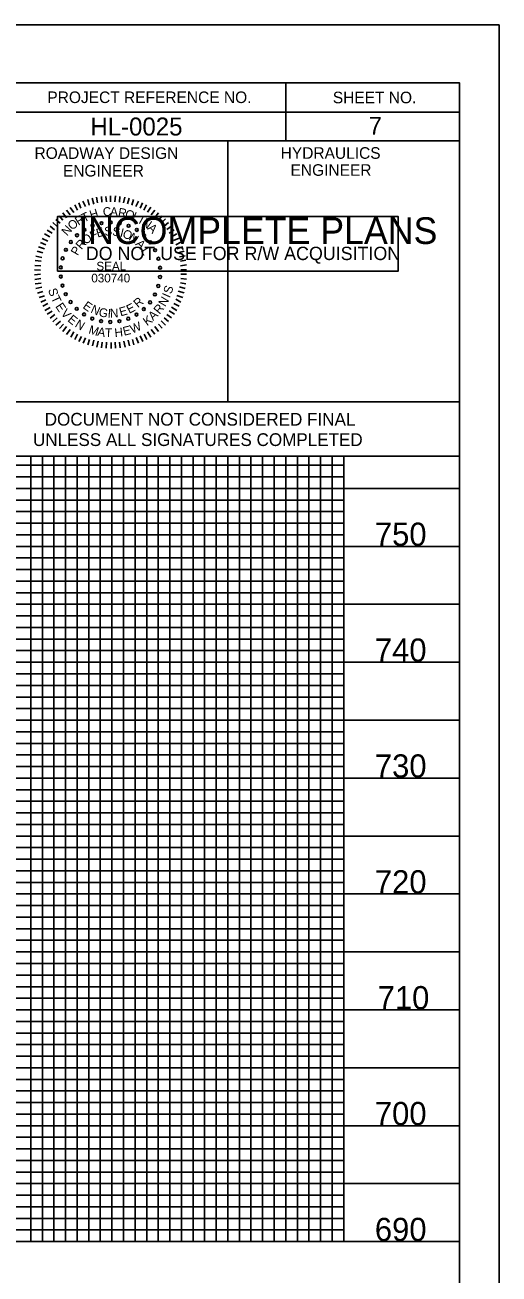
# Model space of a CAD drawing. Extents: x 1524869 to 1526553, y 501099 to 502199.
# Drawn here: x 1526349 to 1526553, y 501660 to 502199 of the extents above; entities that cross this region are included whole.
import ezdxf

# ---------------------------------------------------------------- set-up
doc = ezdxf.new("R2010")
doc.units = 0
for name, color, linetype in [('Exist Vertical Profile Vertical Axis Label', 7, 'Continuous'), ('Old_Level_9', 7, 'Continuous'), ('Sheet Data Field CELL', 7, 'Continuous'), ('Sheet Plot Border Outside CELL', 7, 'Continuous'), ('Sheet Profile CELL', 7, 'Continuous'), ('Sheet Profile Grid Major CELL', 7, 'Continuous'), ('Sheet Profile Grid Middle CELL', 7, 'Continuous'), ('Sheet Profile Grid Minor CELL', 7, 'Continuous'), ('Sheet Sticker Exception Certification CELL', 7, 'Continuous'), ('Sheet Sticker Incomplete CELL', 7, 'Continuous')]:
    doc.layers.add(name, color=color, linetype=linetype)

msp = doc.modelspace()

# ---------------------------------------------------------------- linework, layer by layer
at = {"layer": 'Old_Level_9'}
for p, q in [((1526371.83, 502121.79), (1526372.73, 502119.49)), ((1526373.53, 502122.59), (1526374.73, 502120.19)), ((1526375.63, 502123.19), (1526376.33, 502120.79)), ((1526377.53, 502123.79), (1526378.23, 502121.29)), ((1526379.43, 502124.19), (1526379.93, 502121.79)), ((1526381.53, 502124.49), (1526381.73, 502122.09)), ((1526383.43, 502124.59), (1526383.73, 502122.19)), ((1526385.53, 502124.79), (1526385.53, 502122.19)), ((1526387.63, 502124.79), (1526387.33, 502122.19)), ((1526389.53, 502124.49), (1526389.33, 502122.09)), ((1526391.63, 502124.19), (1526391.13, 502121.79)), ((1526393.53, 502123.79), (1526392.83, 502121.39)), ((1526395.43, 502123.19), (1526394.73, 502120.79)), ((1526397.53, 502122.59), (1526396.33, 502120.19)), ((1526399.23, 502121.79), (1526398.33, 502119.49)), ((1526364.93, 502117.49), (1526366.53, 502115.39)), ((1526366.53, 502118.69), (1526368.03, 502116.69)), ((1526368.13, 502119.79), (1526369.63, 502117.59)), ((1526370.03, 502120.99), (1526371.23, 502118.59)), ((1526401.03, 502120.99), (1526399.83, 502118.59)), ((1526402.93, 502119.99), (1526401.43, 502117.79)), ((1526404.53, 502118.69), (1526403.03, 502116.69)), ((1526406.13, 502117.49), (1526404.53, 502115.49)), ((1526359.43, 502111.69), (1526361.33, 502110.09)), ((1526360.53, 502113.29), (1526362.43, 502111.59)), ((1526361.93, 502114.69), (1526363.73, 502112.99)), ((1526363.33, 502116.19), (1526364.93, 502114.29)), ((1526407.73, 502116.19), (1526406.13, 502114.39)), ((1526409.13, 502114.89), (1526407.33, 502112.99)), ((1526410.53, 502113.29), (1526408.63, 502111.69)), ((1526411.83, 502111.69), (1526409.73, 502110.29)), ((1526356.03, 502106.49), (1526358.43, 502105.29)), ((1526357.03, 502108.39), (1526359.23, 502107.09)), ((1526358.13, 502109.99), (1526360.33, 502108.69)), ((1526412.93, 502110.09), (1526410.83, 502108.69)), ((1526414.03, 502108.39), (1526411.83, 502107.09)), ((1526415.03, 502106.59), (1526412.63, 502105.49)), ((1526353.83, 502100.89), (1526356.33, 502100.19)), ((1526354.43, 502102.79), (1526357.03, 502101.99)), ((1526355.23, 502104.69), (1526357.63, 502103.69)), ((1526415.83, 502104.89), (1526413.63, 502103.69)), ((1526416.63, 502102.79), (1526414.03, 502101.99)), ((1526417.23, 502100.89), (1526414.73, 502100.19)), ((1526352.83, 502094.79), (1526355.43, 502094.69)), ((1526353.03, 502096.89), (1526355.53, 502096.59)), ((1526353.33, 502098.79), (1526355.83, 502098.29)), ((1526417.73, 502098.99), (1526415.23, 502098.49)), ((1526418.03, 502097.09), (1526415.63, 502096.59)), ((1526418.23, 502094.99), (1526415.63, 502094.69)), ((1526352.73, 502092.89), (1526355.23, 502092.69)), ((1526352.73, 502090.79), (1526355.23, 502090.99)), ((1526418.33, 502092.89), (1526415.83, 502092.89)), ((1526418.33, 502090.99), (1526415.83, 502090.99)), ((1526352.83, 502088.79), (1526355.43, 502089.09)), ((1526353.03, 502086.79), (1526355.53, 502087.19)), ((1526353.33, 502084.79), (1526355.83, 502085.39)), ((1526417.73, 502084.89), (1526415.23, 502085.59)), ((1526418.03, 502086.79), (1526415.63, 502087.29)), ((1526418.23, 502088.89), (1526415.83, 502089.09)), ((1526353.93, 502082.89), (1526356.33, 502083.49)), ((1526354.63, 502080.99), (1526357.03, 502081.69)), ((1526355.43, 502078.99), (1526357.63, 502079.99)), ((1526415.83, 502078.99), (1526413.63, 502080.19)), ((1526416.63, 502080.99), (1526414.03, 502081.89)), ((1526417.23, 502082.99), (1526414.73, 502083.69)), ((1526356.23, 502077.29), (1526358.43, 502078.39)), ((1526357.13, 502075.39), (1526359.43, 502076.59)), ((1526358.13, 502073.79), (1526360.33, 502075.09)), ((1526359.43, 502071.99), (1526361.43, 502073.59)), ((1526411.83, 502072.19), (1526409.73, 502073.59)), ((1526413.13, 502073.79), (1526410.83, 502075.19)), ((1526414.03, 502075.39), (1526411.83, 502076.79)), ((1526415.03, 502077.29), (1526412.83, 502078.39)), ((1526360.63, 502070.39), (1526362.53, 502072.19)), ((1526361.93, 502068.99), (1526363.83, 502070.69)), ((1526363.53, 502067.59), (1526365.13, 502069.49)), ((1526364.93, 502066.29), (1526366.53, 502068.39)), ((1526406.23, 502066.29), (1526404.53, 502068.39)), ((1526407.73, 502067.69), (1526406.13, 502069.49)), ((1526409.13, 502068.99), (1526407.33, 502070.89)), ((1526410.53, 502070.59), (1526408.63, 502072.19)), ((1526366.53, 502064.99), (1526368.03, 502067.09)), ((1526368.33, 502063.89), (1526369.63, 502066.09)), ((1526370.03, 502062.89), (1526371.23, 502065.19)), ((1526371.83, 502061.99), (1526372.93, 502064.19)), ((1526373.73, 502061.19), (1526374.73, 502063.59)), ((1526375.63, 502060.49), (1526376.43, 502062.89)), ((1526377.73, 502060.09), (1526378.23, 502062.49)), ((1526393.63, 502060.09), (1526393.03, 502062.49)), ((1526395.53, 502060.49), (1526394.93, 502062.89)), ((1526397.53, 502061.19), (1526396.53, 502063.69)), ((1526399.43, 502061.99), (1526398.33, 502064.39)), ((1526401.13, 502062.89), (1526400.03, 502065.19)), ((1526402.93, 502063.89), (1526401.43, 502066.09)), ((1526404.53, 502065.19), (1526403.03, 502067.19)), ((1526379.63, 502059.59), (1526380.13, 502062.09)), ((1526381.53, 502059.29), (1526381.83, 502061.69)), ((1526383.63, 502059.09), (1526383.73, 502061.69)), ((1526385.73, 502058.99), (1526385.73, 502061.49)), ((1526387.63, 502059.09), (1526387.43, 502061.69)), ((1526389.63, 502059.29), (1526389.33, 502061.69)), ((1526391.73, 502059.59), (1526391.23, 502062.09))]:
    msp.add_line(p, q, dxfattribs=at)
for centre in [(1526377.76, 502111.96), (1526381.58, 502113.03), (1526385.53, 502113.38), (1526389.48, 502113), (1526393.29, 502111.9), (1526368.35, 502104.91), (1526371.03, 502107.83), (1526374.2, 502110.2), (1526396.83, 502110.12), (1526399.98, 502107.71), (1526366.25, 502101.54), (1526402.64, 502104.77), (1526404.72, 502101.39), (1526364.8, 502097.85), (1526406.13, 502097.69), (1526364.04, 502089.99), (1526364.05, 502093.96), (1526406.83, 502089.82), (1526406.85, 502093.79), (1526364.75, 502086.09), (1526406.09, 502085.93), (1526366.17, 502082.39), (1526368.25, 502079.01), (1526402.54, 502078.87), (1526404.64, 502082.24), (1526370.91, 502076.07), (1526374.06, 502073.66), (1526396.68, 502073.58), (1526399.86, 502075.95), (1526377.6, 502071.88), (1526381.41, 502070.78), (1526385.36, 502070.4), (1526389.31, 502070.75), (1526393.13, 502071.82)]:
    msp.add_circle(centre, 0.63, dxfattribs=at)
at = {"layer": 'Sheet Plot Border Outside CELL'}
msp.add_lwpolyline([(1524869.08, 501098.56), (1526553.08, 501098.56), (1526553.08, 502198.56), (1524869.08, 502198.56)], close=True, dxfattribs=at)
at = {"layer": 'Sheet Profile CELL'}
for p, q in [((1526461.08, 502173.51), (1526461.08, 502148.51)), ((1526336.03, 502161.01), (1526536.08, 502161.01)), ((1526436.08, 502148.51), (1526436.08, 502036.06)), ((1525036.08, 501673.56), (1526536.08, 501673.56))]:
    msp.add_line(p, q, dxfattribs=at)
for points in [[(1526536.08, 502173.56), (1525036.08, 502173.56), (1525036.08, 501123.56), (1526536.08, 501123.56)], [(1526336.03, 502173.56), (1526536.08, 502173.56), (1526536.08, 502148.51), (1526336.03, 502148.51)], [(1526336.03, 502148.51), (1526436.08, 502148.51), (1526436.08, 502036.01), (1526336.03, 502036.01)], [(1526436.08, 502148.51), (1526536.08, 502148.51), (1526536.08, 502036.01), (1526436.08, 502036.01)]]:
    msp.add_lwpolyline(points, close=True, dxfattribs=at)
at = {"layer": 'Sheet Profile Grid Major CELL'}
for points in [[(1525986.08, 501673.56), (1526036.08, 501673.56), (1526036.08, 502173.56), (1526086.08, 502173.56), (1526086.08, 501673.56), (1526136.08, 501673.56), (1526136.08, 502173.56), (1526186.08, 502173.56), (1526186.08, 501673.56), (1526236.08, 501673.56), (1526236.08, 502173.56), (1526286.08, 502173.56), (1526286.08, 501673.56), (1526336.08, 501673.56), (1526336.08, 502173.56), (1526362.38, 502173.56)], [(1526486.08, 502012.51), (1526486.08, 501673.56), (1526536.08, 501673.56), (1526536.08, 502023.56)], [(1526386.08, 502012.51), (1526386.08, 501673.56), (1526436.08, 501673.56), (1526436.08, 501673.56), (1526436.08, 502012.51)], [(1526536.08, 501973.56), (1525036.08, 501973.56), (1525036.08, 501923.56), (1526536.08, 501923.56)], [(1526536.08, 501873.56), (1525036.08, 501873.56), (1525036.08, 501823.56), (1526536.08, 501823.56)], [(1526536.08, 501773.56), (1525036.08, 501773.56), (1525036.08, 501773.56), (1525036.08, 501723.56), (1526536.08, 501723.56)]]:
    msp.add_lwpolyline(points, dxfattribs=at)
at = {"layer": 'Sheet Profile Grid Middle CELL'}
for points in [[(1526011.08, 501673.56), (1526061.08, 501673.56), (1526061.08, 502173.56), (1526111.08, 502173.56), (1526111.08, 501673.56), (1526161.08, 501673.56), (1526161.08, 502173.56), (1526211.08, 502173.56), (1526211.08, 501673.56), (1526261.08, 501673.56), (1526261.08, 502173.56), (1526311.08, 502173.56), (1526311.08, 501673.56), (1526361.08, 501673.56), (1526361.08, 502012.51)], [(1526361.08, 501936.36), (1526361.08, 501673.56), (1526411.08, 501673.56), (1526411.08, 502012.51)], [(1526411.08, 501936.36), (1526411.08, 501673.56), (1526461.08, 501673.56), (1526461.08, 502012.51)], [(1526536.08, 501998.56), (1525036.08, 501998.56), (1525036.08, 501948.56), (1526361.08, 501948.56)], [(1526361.08, 501948.56), (1526536.08, 501948.56)], [(1526536.08, 501898.56), (1525036.08, 501898.56), (1525036.08, 501848.56), (1526536.08, 501848.56)], [(1526536.08, 501798.56), (1525036.08, 501798.56), (1525036.08, 501748.56), (1526536.08, 501748.56)], [(1526536.08, 501698.56), (1525036.08, 501698.56)]]:
    msp.add_lwpolyline(points, dxfattribs=at)
at = {"layer": 'Sheet Profile Grid Minor CELL'}
for p, q in [((1526036.08, 502008.56), (1526486.08, 502008.56)), ((1526486.08, 501988.56), (1526036.08, 501988.56)), ((1526036.08, 501983.56), (1526486.08, 501983.56)), ((1526486.08, 501963.56), (1526036.08, 501963.56)), ((1526036.08, 501958.56), (1526486.08, 501958.56)), ((1526486.08, 501938.56), (1526036.08, 501938.56)), ((1526036.08, 501933.56), (1526486.08, 501933.56)), ((1526486.08, 501928.56), (1526036.08, 501928.56)), ((1526036.08, 501918.56), (1526486.08, 501918.56)), ((1526486.08, 501913.56), (1526036.08, 501913.56)), ((1526036.08, 501908.56), (1526486.08, 501908.56)), ((1526486.08, 501903.56), (1526036.08, 501903.56)), ((1526036.08, 501893.56), (1526486.08, 501893.56)), ((1526486.08, 501888.56), (1526036.08, 501888.56)), ((1526036.08, 501883.56), (1526486.08, 501883.56)), ((1526486.08, 501878.56), (1526036.08, 501878.56)), ((1526036.08, 501868.56), (1526486.08, 501868.56)), ((1526486.08, 501863.56), (1526036.08, 501863.56)), ((1526036.08, 501858.56), (1526486.08, 501858.56)), ((1526486.08, 501853.56), (1526036.08, 501853.56)), ((1526036.08, 501843.56), (1526486.08, 501843.56)), ((1526486.08, 501838.56), (1526036.08, 501838.56)), ((1526036.08, 501833.56), (1526486.08, 501833.56)), ((1526486.08, 501828.56), (1526036.08, 501828.56)), ((1526036.08, 501818.56), (1526486.08, 501818.56)), ((1526486.08, 501813.56), (1526036.08, 501813.56)), ((1526036.08, 501808.56), (1526486.08, 501808.56)), ((1526486.08, 501803.56), (1526036.08, 501803.56)), ((1526036.08, 501793.56), (1526486.08, 501793.56)), ((1526486.08, 501788.56), (1526036.08, 501788.56)), ((1526486.08, 501783.56), (1526036.08, 501783.56)), ((1526486.08, 501778.56), (1526036.08, 501778.56)), ((1526036.08, 501768.56), (1526486.08, 501768.56)), ((1526486.08, 501763.56), (1526036.08, 501763.56)), ((1526036.08, 501758.56), (1526486.08, 501758.56)), ((1526486.08, 501753.56), (1526036.08, 501753.56)), ((1526036.08, 501743.56), (1526486.08, 501743.56)), ((1526486.08, 501738.56), (1526036.08, 501738.56)), ((1526036.08, 501733.56), (1526486.08, 501733.56)), ((1526486.08, 501728.56), (1526036.08, 501728.56)), ((1526036.08, 501718.56), (1526486.08, 501718.56)), ((1526486.08, 501713.56), (1526036.08, 501713.56)), ((1526036.08, 501708.56), (1526486.08, 501708.56)), ((1526486.08, 501703.56), (1526036.08, 501703.56)), ((1526036.08, 501693.56), (1526486.08, 501693.56)), ((1526486.08, 501688.56), (1526036.08, 501688.56)), ((1526036.08, 501683.56), (1526486.08, 501683.56))]:
    msp.add_line(p, q, dxfattribs=at)
for points in [[(1526351.08, 502012.51), (1526351.08, 501673.56), (1526356.08, 501673.56), (1526356.08, 502012.51)], [(1526366.08, 502012.51), (1526366.08, 501673.56), (1526366.08, 501673.56), (1526371.08, 501673.56), (1526376.08, 501673.56), (1526376.08, 502012.51)], [(1526371.08, 502012.51), (1526371.08, 501673.56)], [(1526381.07, 502012.51), (1526380.98, 501673.61), (1526385.98, 501673.61), (1526391.08, 501673.56), (1526391.08, 502012.51)], [(1526391.08, 501936.36), (1526391.08, 501673.56), (1526396.08, 501673.56), (1526396.08, 502012.51)], [(1526401.08, 502012.51), (1526401.08, 501673.56), (1526406.08, 501673.56), (1526406.08, 502012.51)], [(1526416.08, 502012.51), (1526416.08, 501673.56), (1526421.08, 501673.56), (1526421.08, 502012.51)], [(1526426.08, 502012.51), (1526426.08, 501673.56), (1526431.08, 501673.56), (1526431.08, 502012.51)], [(1526441.08, 502012.51), (1526441.08, 501673.56), (1526446.08, 501673.56), (1526446.08, 502012.51)], [(1526451.08, 502012.51), (1526451.08, 501673.56), (1526456.08, 501673.56), (1526456.08, 502012.51)], [(1526466.08, 502012.51), (1526466.08, 501673.56), (1526471.08, 501673.56), (1526471.08, 502012.51)], [(1526476.08, 502012.51), (1526476.08, 501673.56), (1526481.08, 501673.56), (1526481.08, 502012.51)], [(1526486.08, 502003.56), (1526036.08, 502003.56)], [(1526036.08, 501993.56), (1526486.08, 501993.56)], [(1526486.08, 501978.56), (1526036.08, 501978.56)], [(1526036.08, 501968.56), (1526486.08, 501968.56)], [(1526486.08, 501953.56), (1526036.08, 501953.56)], [(1526036.08, 501943.56), (1526486.08, 501943.56)], [(1526486.08, 501678.56), (1526036.08, 501678.56)]]:
    msp.add_lwpolyline(points, dxfattribs=at)
at = {"layer": 'Sheet Sticker Exception Certification CELL'}
for p, q in [((1526336.03, 502036.01), (1526536.07, 502036.01)), ((1526336.03, 502036.01), (1526536.07, 502036.01)), ((1526536.07, 502036), (1526536.07, 502012.5)), ((1526536.07, 502036), (1526536.07, 502012.5)), ((1526536.07, 502012.51), (1526336.03, 502012.51)), ((1526536.07, 502012.51), (1526336.03, 502012.51))]:
    msp.add_line(p, q, dxfattribs=at)
at = {"layer": 'Sheet Sticker Incomplete CELL'}
msp.add_lwpolyline([(1526362.6, 502092.36), (1526362.6, 502115.86), (1526509.6, 502115.86), (1526509.6, 502092.36)], close=True, dxfattribs=at)

# ---------------------------------------------------------------- texts
at = {"layer": 'Exist Vertical Profile Vertical Axis Label'}
for s, p in [('750', (1526499.51, 501973.81)), ('740', (1526499.51, 501923.81)), ('730', (1526499.51, 501873.81)), ('720', (1526499.51, 501823.81)), ('710', (1526500.71, 501773.81)), ('700', (1526499.51, 501723.81)), ('690', (1526499.51, 501673.81))]:
    msp.add_text(s, height=10, dxfattribs=at).set_placement(p)
at = {"layer": 'Old_Level_9'}
for s, height, rotation, p in [('R', 3.78, 32.1754, (1526371.63, 502111.89)), ('T', 3.78, 25.4358, (1526374.03, 502113.29)), ('H', 3.78, 17.7433, (1526377.13, 502114.69)), ('C', 3.78, 4.9399, (1526382.33, 502115.99)), ('A', 3.78, 357.9749, (1526385.23, 502116.19)), ('R', 3.78, 350.0216, (1526388.53, 502115.99)), ('O', 3.78, 343.0868, (1526391.43, 502115.49)), ('L', 3.78, 335.7459, (1526394.43, 502114.59)), ('I', 3.78, 330.806, (1526397.33, 502113.19)), ('N', 3.78, 48.0667, (1526366.73, 502107.29)), ('O', 3.78, 39.9442, (1526368.93, 502109.79)), ('E', 3.76, 16.5889, (1526379.93, 502106.79)), ('S', 3.76, 4.468, (1526382.93, 502107.59)), ('S', 3.76, 353.0415, (1526386.13, 502107.69)), ('N', 3.78, 324.9038, (1526398.63, 502112.49)), ('A', 3.78, 317.0051, (1526401.13, 502110.59)), ('R', 3.76, 49.7478, (1526372.93, 502101.39)), ('O', 3.76, 38.2518, (1526374.83, 502103.59)), ('F', 3.76, 26.4, (1526377.73, 502105.69)), ('I', 3.76, 345.4821, (1526389.33, 502107.29)), ('O', 3.76, 337.8749, (1526390.33, 502107.09)), ('N', 3.76, 327.393, (1526393.03, 502105.99)), ('A', 3.76, 313.9438, (1526396.03, 502103.89)), ('P', 3.76, 60.1236, (1526371.33, 502098.79)), ('L', 3.76, 301.5323, (1526398.43, 502101.19)), ('S', 3.78, 288.212, (1526358.48, 502084.31)), ('S', 3.78, 72.2579, (1526411.71, 502082.2)), ('T', 3.78, 295.6244, (1526359.67, 502080.79)), ('E', 3.78, 303.8225, (1526361.54, 502077.11)), ('E', 3.76, 324.8692, (1526373.23, 502076.59)), ('E', 3.76, 27.1568, (1526393.53, 502073.89)), ('R', 3.76, 40.3493, (1526397.33, 502076.29)), ('N', 3.78, 59.3726, (1526409.08, 502076.71)), ('I', 3.78, 66.0464, (1526411.01, 502080.51)), ('V', 3.78, 311.9298, (1526363.8, 502073.93)), ('E', 3.78, 320.2312, (1526366.69, 502070.96)), ('N', 3.76, 336.0584, (1526376.63, 502074.59)), ('G', 3.76, 347.4812, (1526380.13, 502072.99)), ('I', 3.76, 355.6246, (1526384.13, 502072.29)), ('N', 3.76, 3.1278, (1526385.33, 502072.29)), ('E', 3.76, 15.8057, (1526389.83, 502072.79)), ('K', 3.78, 36.141, (1526401.23, 502068.53)), ('A', 3.78, 43.5217, (1526403.86, 502070.8)), ('R', 3.78, 51.1503, (1526406.62, 502073.47)), ('N', 3.78, 328.329, (1526369.82, 502068.53)), ('M', 3.78, 342.337, (1526375.73, 502065.53)), ('A', 3.78, 350.1822, (1526379.62, 502064.5)), ('H', 3.78, 6.0112, (1526387.38, 502063.83)), ('E', 3.78, 14.1648, (1526391.32, 502064.41)), ('W', 3.78, 22.0058, (1526394.78, 502065.37)), ('T', 3.78, 357.3866, (1526383.03, 502063.94))]:
    msp.add_text(s, height=height, rotation=rotation, dxfattribs=at).set_placement(p)
for s, p in [('SEAL', (1526379.39, 502092.63)), ('030740', (1526377.19, 502087.47))]:
    msp.add_text(s, height=3.759, dxfattribs=at).set_placement(p)
at = {"layer": 'Sheet Data Field CELL'}
for s, p in [('HL-0025', (1526376.78, 502150.87)), ('7', (1526496.83, 502151.17))]:
    msp.add_text(s, height=7.75, dxfattribs=at).set_placement(p)
at = {"layer": 'Sheet Profile CELL'}
for s, height, p in [('PROJECT REFERENCE NO.', 5.0001, (1526358.24, 502164.87)), ('SHEET NO.', 5, (1526481.39, 502164.77)), ('ROADWAY DESIGN', 5.0001, (1526352.69, 502140.77)), ('HYDRAULICS', 5, (1526458.89, 502140.82)), ('ENGINEER', 5, (1526364.94, 502133.17)), ('ENGINEER', 5, (1526463.14, 502133.47))]:
    msp.add_text(s, height=height, dxfattribs=at).set_placement(p)
at = {"layer": 'Sheet Sticker Exception Certification CELL'}
for s, p in [('DOCUMENT NOT CONSIDERED FINAL', (1526357.1, 502025.67)), ('DOCUMENT NOT CONSIDERED FINAL', (1526357.1, 502025.67)), ('UNLESS ALL SIGNATURES COMPLETED', (1526352.03, 502016.87)), ('UNLESS ALL SIGNATURES COMPLETED', (1526352.03, 502016.87))]:
    msp.add_text(s, height=5.5, dxfattribs=at).set_placement(p)
at = {"layer": 'Sheet Sticker Incomplete CELL'}
for s, height, p in [('INCOMPLETE PLANS', 11.52, (1526371.55, 502104.06)), ('DO NOT USE FOR R/W ACQUISITION', 5.76, (1526374.8, 502097.11))]:
    msp.add_text(s, height=height, dxfattribs=at).set_placement(p)

doc.saveas('drawing.dxf')
